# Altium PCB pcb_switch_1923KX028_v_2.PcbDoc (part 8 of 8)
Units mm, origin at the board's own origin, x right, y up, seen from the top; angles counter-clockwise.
Board outline 297.2 x 112.05 mm, 6 copper layers (Component Side, GND Layer 1, Inner Layer 1, Inner Layer 2, GND Layer 2, Solder Side), stack 1.578 mm thick; 545 components, 377 nets, 3174 pads, 1537 vias.
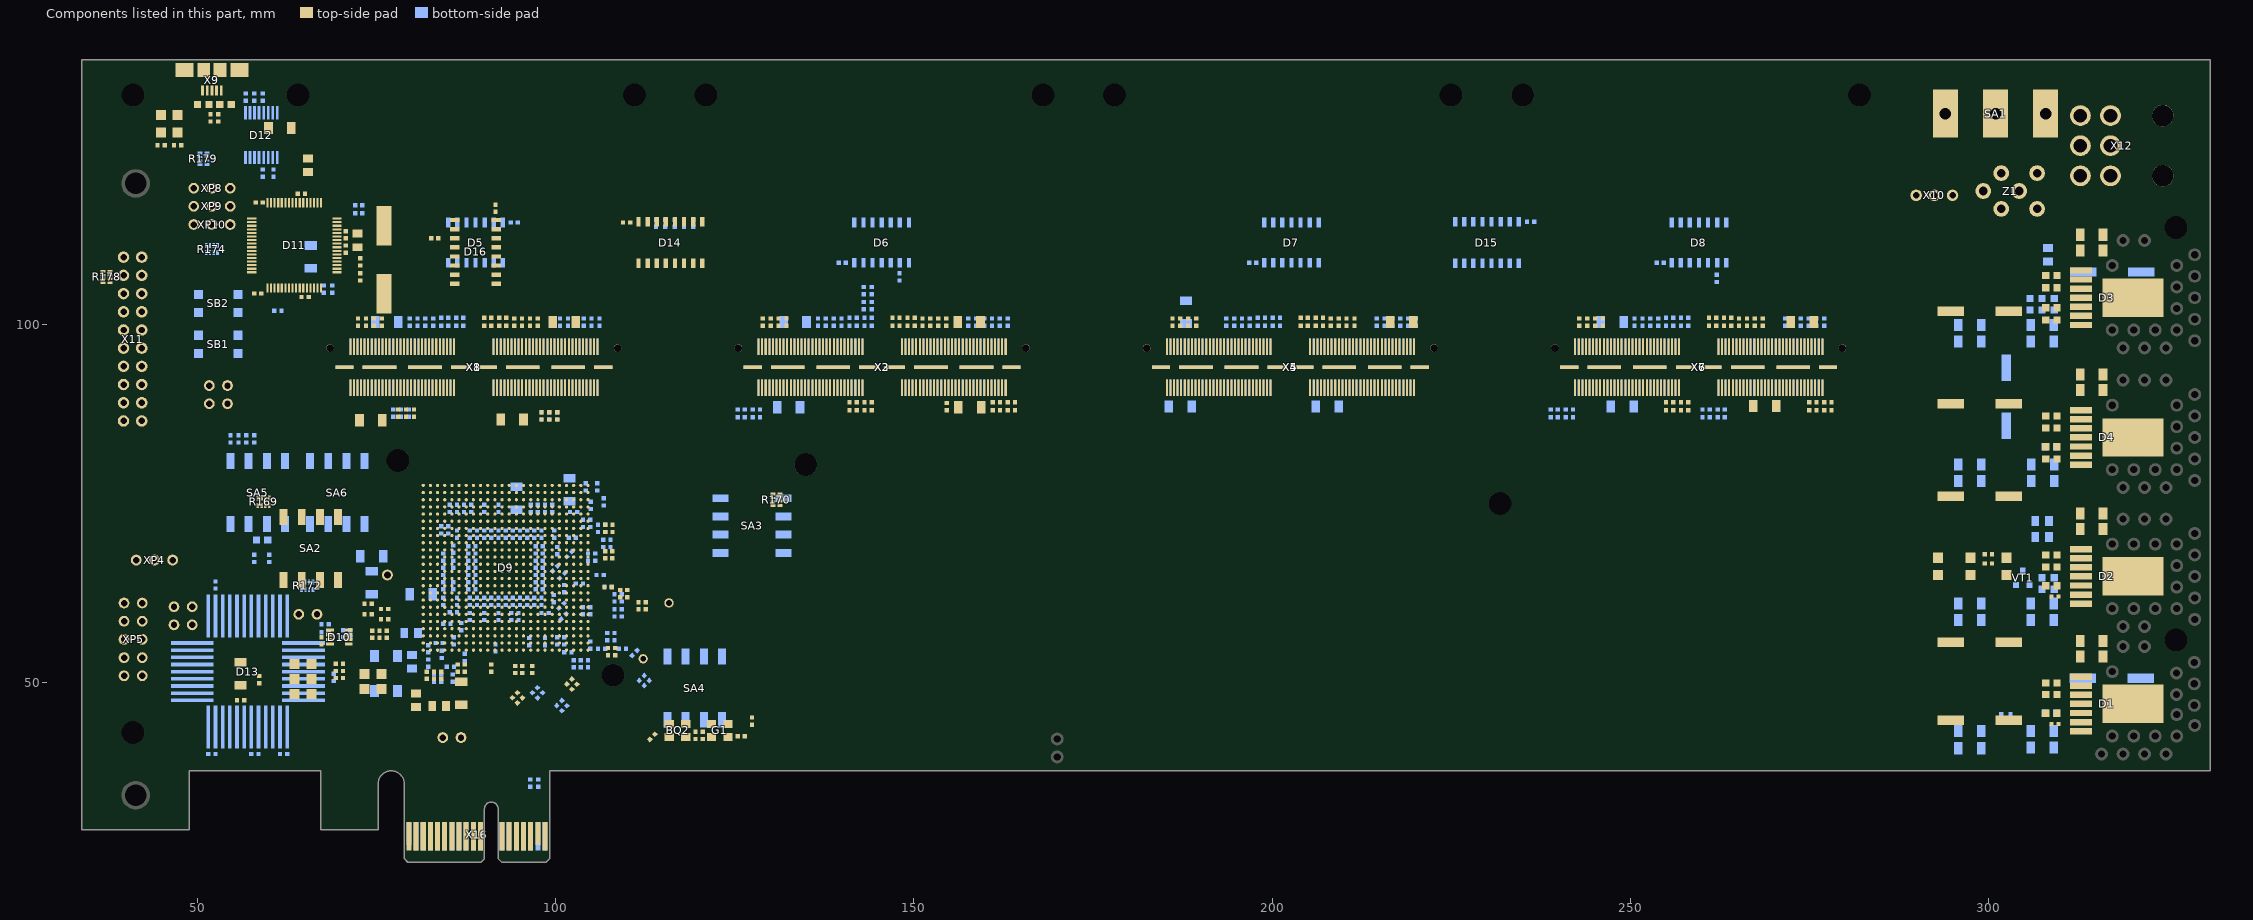
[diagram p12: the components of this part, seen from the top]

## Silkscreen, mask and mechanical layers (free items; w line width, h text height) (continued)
Mechanical 1:
  circle w0.18: c326.2,55.9 r1.6
  circle w0.18: c326.2,113.5 r1.6
  circle w0.18: c231.8,75 r1.6
  circle w0.18: c108,51 r1.6
  circle w0.18: c41.4,34.3 r1.6
  circle w0.18: c41,43 r1.6
  circle w0.18: c78,81 r1.6
  circle w0.18: c41.4,119.7 r1.6
  circle w0.18: c41,132 r1.6
  lines w0.15: 34.4,30.2 43.7,30.2 ccw(c43.7,31.2) 44.7,31.2 44.7,37.3 ccw(c43.7,37.3) 43.7,38.3 34.4,38.3 ; 34.4,115.6 43.7,115.6 ccw(c43.7,116.6) 44.7,116.6 44.7,122.7 ccw(c43.7,122.7) 43.7,123.7 34.4,123.7
  lines w0.2: 79.25,26.6 79.25,30.4 79.75,30.4 79.75,26.6 79.25,26.6 ; 80.25,26.6 80.75,26.6 80.75,30.4 80.25,30.4 80.25,26.6 ; 81.25,26.6 81.75,26.6 81.75,30.4 81.25,30.4 81.25,26.6 ; 82.25,26.6 82.75,26.6 82.75,30.4 82.25,30.4 82.25,26.6 ; 83.25,26.6 83.75,26.6 83.75,30.4 83.25,30.4 83.25,26.6 ; 84.25,26.6 84.75,26.6 84.75,30.4 84.25,30.4 84.25,26.6 ; 85.25,26.6 85.75,26.6 85.75,30.4 85.25,30.4 85.25,26.6 ; 86.25,26.6 86.75,26.6 86.75,30.4 86.25,30.4 86.25,26.6 ; 87.25,26.6 87.75,26.6 87.75,30.4 87.25,30.4 87.25,26.6 ; 88.25,26.6 88.75,26.6 88.75,30.4 88.25,30.4 88.25,26.6 ; 89.25,26.6 89.75,26.6 89.75,30.4 89.25,30.4 89.25,26.6 ; 92.25,26.6 92.75,26.6 92.75,30.4 92.25,30.4 92.25,26.6 ; 93.25,26.6 93.75,26.6 93.75,30.4 93.25,30.4 93.25,26.6 ; 94.25,26.6 94.75,26.6 94.75,30.4 94.25,30.4 94.25,26.6 ; 95.25,26.6 95.75,26.6 95.75,30.4 95.25,30.4 95.25,26.6 ; 96.25,26.6 96.75,26.6 96.75,30.4 96.25,30.4 96.25,26.6 ; 97.25,27.4 97.75,27.4 97.75,30.4 97.25,30.4 97.25,27.4 ; 98.25,26.6 98.75,26.6 98.75,30.4 98.25,30.4 98.25,26.6
  lines w0.254: 318.15,118.025 318.15,119.625 ; 318.15,121.875 318.15,123.75 ; 318.15,126 318.15,127.875 ; 318.15,130.25 318.15,131.825
Mechanical 2:
  circle w0.18: c134.9,80.4 r1.562
  circle w0.18: c64,132 r1.562
  circle w0.18: c121,132 r1.562
  circle w0.18: c111,132 r1.562
  circle w0.18: c168,132 r1.562
  circle w0.18: c178,132 r1.562
  circle w0.18: c225,132 r1.562
  circle w0.18: c235,132 r1.562
  circle w0.18: c282,132 r1.562
  circle w0.18: c326.2,113.5 r1.562
  circle w0.18: c326.2,55.9 r1.562
  circle w0.18: c231.8,75 r1.562
  circle w0.18: c78,81 r1.562
  circle w0.18: c108,51 r1.562
  circle w0.18: c41,43 r1.562
  circle w0.18: c41.4,34.3 r1.562
  circle w0.18: c41.4,119.7 r1.562
  circle w0.18: c41,132 r1.562
  circle w0.18: c269,113.5 r1.562
  lines w0.15: 78.85,26.3 90.05,26.3 ; 91.95,26.3 99.15,26.3
  lines w0.2: 79.25,27.4 79.75,27.4 79.75,30.4 79.25,30.4 79.25,27.4 ; 80.25,26.6 80.75,26.6 80.75,30.4 80.25,30.4 80.25,26.6 ; 81.25,26.6 81.75,26.6 81.75,30.4 81.25,30.4 81.25,26.6 ; 82.25,26.6 82.75,26.6 82.75,30.4 82.25,30.4 82.25,26.6 ; 83.25,26.6 83.75,26.6 83.75,30.4 83.25,30.4 83.25,26.6 ; 84.25,26.6 84.75,26.6 84.75,30.4 84.25,30.4 84.25,26.6 ; 85.25,26.6 85.75,26.6 85.75,30.4 85.25,30.4 85.25,26.6 ; 86.25,26.6 86.75,26.6 86.75,30.4 86.25,30.4 86.25,26.6 ; 87.25,26.6 87.75,26.6 87.75,30.4 87.25,30.4 87.25,26.6 ; 88.25,26.6 88.75,26.6 88.75,30.4 88.25,30.4 88.25,26.6 ; 89.25,26.6 89.75,26.6 89.75,30.4 89.25,30.4 89.25,26.6 ; 92.25,26.6 92.75,26.6 92.75,30.4 92.25,30.4 92.25,26.6 ; 93.25,26.6 93.75,26.6 93.75,30.4 93.25,30.4 93.25,26.6 ; 94.25,26.6 94.75,26.6 94.75,30.4 94.25,30.4 94.25,26.6 ; 95.25,26.6 95.75,26.6 95.75,30.4 95.25,30.4 95.25,26.6 ; 96.25,26.6 96.75,26.6 96.75,30.4 96.25,30.4 96.25,26.6 ; 97.25,26.6 97.75,26.6 97.75,30.4 97.25,30.4 97.25,26.6 ; 98.25,26.6 98.25,30.4 98.75,30.4 98.75,26.6 98.25,26.6
Mechanical 3:
  the board outline again, w0.2
Mechanical 4:
  lines w0.15: 103,56 103.5,56.5 111.5,56.5 113.9,54.1 113.9,53.6 114.5,53 119.5,53 ; 103,57 103.6,57.6 112.1,57.6 116.2,53.5 117,53.5 ; 104,56 111.3,56 113.5,53.8 113.5,53.4 114,52.9 114,52.6 114.2,52.4 117,52.4 125.1,44.3 ; 104,57 111.8,57 114.5,54.3 114.5,53.9
  text "Стек печатной платы: /   материал: «Kingboard»KB-6167F (Tg170) /   ядро: FR-4, 0.51 ± 0.05 mm,  Dk: 4.7 /   препрег: prepreg 1080, 0.069 ± 0.008 mm, Dk: 4.2 ± 0.25 /    /  6-ти слойная печатная плата: /     Top layer: 0.018 mm  /         2 x prepreg 1080 (0.15 mm) /     GND 1  layer: 0.018 mm /         Core: 0.51 mm /     Inner 1 Layer: 0.018 mm /         2 x prepreg 1080 (0.15 mm) /     Inner 2 Layer: 0.018 mm /         Core: 0.51 mm /     GND 2  Layer: 0.018 mm  /         2 x prepreg 1080 (0.015 mm) /     Bottom Layer 0.018 mm /      / Дифф. пара: /     ширина трассы (W): 0.15 мм /     расстояние между трассами (S): 0.16 мм /     расстояние до полигона \"GND\" (D1): 0.20 мм /     толщина медной фольги (Т1): 0.018 мм (0.045 мм после металлизации) /  / Дополнительные механические слои: / Mechanical 21 (top), 27 (bottom) - желтый цвет, 100 нФ, 10В, 0402 / Mechanical 22 (top), 28 (bottom) - красный цвет, 1 мкФ, 10В, 0402 / Mechanical 23 (top), 29 (bottom) - зеленый цвет, 10 нФ, 25В, 0402 / Mechanical 24 (top), 30 (bottom) - синий цвет, 1 нФ, 50В, 0402 / Mechanical 25 (top), 31 (bottom) - малиновый цвет, 11 кОм, 1%, 0402 / Mechanical 26 (top), 32 (bottom) - голубой цвет, 2.49 кОм, 1%, 0402" at 339.4,24.3 h5
Mechanical 21:
  rectangle: 308.4,43.8 310.2,44.6
  rectangle: 308.4,61.6 310.2,62.4
  rectangle: 109,113.8 110.8,114.6
  region: 91.2,117.1 91.2,115.3 92,115.3 92,117.1
  region: 93.9,52.7 93.9,50.9 94.7,50.9 94.7,52.7
  region: 94.9,52.7 94.9,50.9 95.7,50.9 95.7,52.7
  rectangle: 111.2,59.8 113,60.6
  rectangle: 111.2,60.8 113,61.6
  region: 101.7,50.4 102.973,49.127 103.538,49.693 102.266,50.966
  region: 101,49.7 102.273,48.427 102.838,48.993 101.566,50.266
  rectangle: 106.9,53.4 108.7,54.2
  rectangle: 106.9,54.4 108.7,55.2
  region: 106.5,72.4 106.5,70.6 107.3,70.6 107.3,72.4
  region: 107.5,72.4 107.5,70.6 108.3,70.6 108.3,72.4
  region: 93.4,47.8 94.673,46.527 95.238,47.093 93.966,48.366
  rectangle: 108.6,61.5 110.4,62.3
  region: 94.1,48.5 95.373,47.227 95.938,47.793 94.666,49.066
  rectangle: 108.6,62.5 110.4,63.3
  region: 66.9,56.7 66.9,54.9 67.7,54.9 67.7,56.7
  region: 70.3,111.4 70.3,109.6 71.1,109.6 71.1,111.4
  region: 70.3,113.4 70.3,111.6 71.1,111.6 71.1,113.4
  rectangle: 57.5,103.9 59.3,104.7
  rectangle: 64.1,103.4 65.9,104.2
  rectangle: 57.7,116.6 59.5,117.4
  rectangle: 63.6,117.8 65.4,118.6
  rectangle: 106.5,67.9 108.3,68.7
  rectangle: 106.5,66.9 108.3,67.7
  region: 86.9,52.9 86.9,51.1 87.7,51.1 87.7,52.9
  rectangle: 106.4,62.9 108.2,63.7
  region: 90.6,52.9 90.6,51.1 91.4,51.1 91.4,52.9
  rectangle: 125,42.1 126.8,42.9
Mechanical 22:
  rectangle: 96.3,50.9 97.1,52.7
  rectangle: 85.9,51.1 86.7,52.9
  region: 56.9,47.1 56.9,47.9 55.1,47.9 55.1,47.1
Mechanical 25:
  rectangle: 79.8,86.7 80.6,88.5
  rectangle: 77.6,86.7 78.4,88.5
  region: 142.4,87.6 142.4,88.4 140.6,88.4 140.6,87.6
  region: 144.5,87.6 144.5,88.4 142.7,88.4 142.7,87.6
  region: 162.4,88.7 162.4,89.5 160.6,89.5 160.6,88.7
  region: 164.5,88.7 164.5,89.5 162.7,89.5 162.7,88.7
  region: 256.4,88.7 256.4,89.5 254.6,89.5 254.6,88.7
  region: 258.5,88.7 258.5,89.5 256.7,89.5 256.7,88.7
  region: 276.4,88.7 276.4,89.5 274.6,89.5 274.6,88.7
  region: 278.5,88.7 278.5,89.5 276.7,89.5 276.7,88.7
  region: 59,51.3 58.2,51.3 58.2,49.5 59,49.5
  region: 84.4,51.9 83.6,51.9 83.6,50.1 84.4,50.1
  region: 127.8,45.5 127,45.5 127,43.7 127.8,43.7
  region: 79.5,88.5 78.7,88.5 78.7,86.7 79.5,86.7
  region: 98.4,88.1 97.6,88.1 97.6,86.3 98.4,86.3
  region: 99.5,88.1 98.7,88.1 98.7,86.3 99.5,86.3
  region: 100.6,88.1 99.8,88.1 99.8,86.3 100.6,86.3
  region: 82.2,112.4 82.2,111.6 84,111.6 84,112.4
Mechanical 26:
  rectangle: 140.6,88.7 142.4,89.5
  rectangle: 142.7,88.7 144.5,89.5
  rectangle: 89.6,99.4 91.4,100.2
  rectangle: 91.7,99.4 93.5,100.2
  rectangle: 146.6,99.4 148.4,100.2
  rectangle: 148.7,99.4 150.5,100.2
  rectangle: 160.6,87.6 162.4,88.4
  rectangle: 162.7,87.6 164.5,88.4
  rectangle: 254.6,87.6 256.4,88.4
  rectangle: 256.7,87.6 258.5,88.4
  rectangle: 203.6,99.4 205.4,100.2
  rectangle: 205.7,99.4 207.5,100.2
  rectangle: 260.6,99.4 262.4,100.2
  rectangle: 262.7,99.4 264.5,100.2
  rectangle: 274.6,87.6 276.4,88.4
  rectangle: 276.7,87.6 278.5,88.4
  region: 72.8,99.4 72.8,101.2 72,101.2 72,99.4
  region: 73.9,99.4 73.9,101.2 73.1,101.2 73.1,99.4
  region: 75,99.4 75,101.2 74.2,101.2 74.2,99.4
  region: 76.1,99.4 76.1,101.2 75.3,101.2 75.3,99.4
  region: 94.6,99.4 94.6,101.2 93.8,101.2 93.8,99.4
  region: 129.3,99.4 129.3,101.2 128.5,101.2 128.5,99.4
  region: 130.4,99.4 130.4,101.2 129.6,101.2 129.6,99.4
  region: 131.5,99.4 131.5,101.2 130.7,101.2 130.7,99.4
  region: 132.6,99.4 132.6,101.2 131.8,101.2 131.8,99.4
  region: 95.7,99.4 95.7,101.2 94.9,101.2 94.9,99.4
  region: 96.8,99.4 96.8,101.2 96,101.2 96,99.4
  region: 97.9,99.4 97.9,101.2 97.1,101.2 97.1,99.4
  region: 151.6,99.4 151.6,101.2 150.8,101.2 150.8,99.4
  region: 154.9,99.4 154.9,101.2 154.1,101.2 154.1,99.4
  region: 152.7,99.4 152.7,101.2 151.9,101.2 151.9,99.4
  region: 153.8,99.4 153.8,101.2 153,101.2 153,99.4
  region: 186.5,99.4 186.5,101.2 185.7,101.2 185.7,99.4
  region: 187.6,99.4 187.6,101.2 186.8,101.2 186.8,99.4
  region: 188.7,99.4 188.7,101.2 187.9,101.2 187.9,99.4
  region: 189.8,99.4 189.8,101.2 189,101.2 189,99.4
  region: 208.6,99.4 208.6,101.2 207.8,101.2 207.8,99.4
  region: 209.7,99.4 209.7,101.2 208.9,101.2 208.9,99.4
  region: 210.8,99.4 210.8,101.2 210,101.2 210,99.4
  region: 211.9,99.4 211.9,101.2 211.1,101.2 211.1,99.4
  region: 243.3,99.4 243.3,101.2 242.5,101.2 242.5,99.4
  region: 244.4,99.4 244.4,101.2 243.6,101.2 243.6,99.4
  region: 245.5,99.4 245.5,101.2 244.7,101.2 244.7,99.4
  region: 246.6,99.4 246.6,101.2 245.8,101.2 245.8,99.4
  region: 265.6,99.4 265.6,101.2 264.8,101.2 264.8,99.4
  region: 266.7,99.4 266.7,101.2 265.9,101.2 265.9,99.4
  region: 267.8,99.4 267.8,101.2 267,101.2 267,99.4
  region: 268.9,99.4 268.9,101.2 268.1,101.2 268.1,99.4
Mechanical 27:
  rectangle: 235.2,113.9 237,114.7
  rectangle: 93.3,113.8 95.1,114.6
  rectangle: 139.1,108.2 140.9,109
  rectangle: 196.4,108.2 198.2,109
  rectangle: 253.3,108.2 255.1,109
  region: 99.6,46.7 100.873,45.427 101.438,45.993 100.166,47.266
  region: 100.3,47.4 101.573,46.127 102.138,46.693 100.866,47.966
  region: 56.3,132.6 56.3,130.8 57.1,130.8 57.1,132.6
  region: 58.7,132.6 58.7,130.8 59.5,130.8 59.5,132.6
  region: 57.5,132.6 57.5,130.8 58.3,130.8 58.3,132.6
  rectangle: 107.8,58.8 109.6,59.6
  rectangle: 107.8,59.8 109.6,60.6
  rectangle: 106.8,55.5 108.6,56.3
  rectangle: 106.8,56.5 108.6,57.3
  rectangle: 106.2,68.5 108,69.3
  rectangle: 106.2,69.5 108,70.3
  region: 96.2,48.5 97.473,47.227 98.038,47.793 96.766,49.066
  rectangle: 107.8,60.9 109.6,61.7
  region: 96.9,49.2 98.173,47.927 98.738,48.493 97.466,49.766
  rectangle: 107.8,61.9 109.6,62.7
  region: 111.7,49.7 112.973,50.973 112.407,51.538 111.134,50.266
  region: 112.4,49 113.673,50.273 113.107,50.838 111.834,49.566
  region: 96.8,35.1 96.8,36.9 96,36.9 96,35.1
  region: 98,35.1 98,36.9 97.2,36.9 97.2,35.1
  region: 90.4,60.4 90.4,62.2 89.6,62.2 89.6,60.4
  region: 96.4,60.4 96.4,62.2 95.6,62.2 95.6,60.4
  region: 93.4,60.4 93.4,62.2 92.6,62.2 92.6,60.4
  region: 89.2,63.4 87.4,63.4 87.4,62.6 89.2,62.6
  region: 98.6,63.4 96.8,63.4 96.8,62.6 98.6,62.6
  region: 89.2,67.4 87.4,67.4 87.4,66.6 89.2,66.6
  region: 98.6,67.4 96.8,67.4 96.8,66.6 98.6,66.6
  region: 95.6,71.6 95.6,69.8 96.4,69.8 96.4,71.6
  region: 92.6,71.6 92.6,69.8 93.4,69.8 93.4,71.6
  region: 89.6,71.6 89.6,69.8 90.4,69.8 90.4,71.6
  rectangle: 108.4,54.3 110.2,55.1
  rectangle: 97.6,59.3 99.4,60.1
  region: 100.5,64 101.773,65.273 101.207,65.838 99.934,64.566
  region: 104.6,76.4 104.6,78.2 103.8,78.2 103.8,76.4
  region: 86.1,65.6 86.1,67.4 85.3,67.4 85.3,65.6
  region: 92.4,73.4 92.4,75.2 91.6,75.2 91.6,73.4
  region: 87.6,73.4 87.6,75.2 86.8,75.2 86.8,73.4
  region: 86,49.7 86,51.5 85.2,51.5 85.2,49.7
  region: 86.6,73.4 86.6,75.2 85.8,75.2 85.8,73.4
  region: 86.1,67.7 86.1,69.5 85.3,69.5 85.3,67.7
  region: 84.7,60.4 84.7,62.2 83.9,62.2 83.9,60.4
  region: 88.4,58.3 88.4,60.1 87.6,60.1 87.6,58.3
  region: 94.2,58.3 94.2,60.1 93.4,60.1 93.4,58.3
  region: 98.9,73.4 98.9,75.2 98.1,75.2 98.1,73.4
  region: 105.9,68.4 104.1,68.4 104.1,67.6 105.9,67.6
  region: 105.9,67.4 104.1,67.4 104.1,66.6 105.9,66.6
  region: 86.2,52.6 84.4,52.6 84.4,51.8 86.2,51.8
  region: 83.7,54.8 83.7,53 84.5,53 84.5,54.8
  rectangle: 103.4,71.3 105.2,72.1
  rectangle: 102.4,63.4 104.2,64.2
  rectangle: 103.4,60.1 105.2,60.9
  region: 83.4,49.7 83.4,51.5 82.6,51.5 82.6,49.7
  region: 98.9,54.8 98.9,56.6 98.1,56.6 98.1,54.8
  region: 101.6,55.7 99.8,55.7 99.8,54.9 101.6,54.9
  region: 102.1,53.5 102.1,51.7 102.9,51.7 102.9,53.5
  region: 105.5,72.4 105.5,70.6 106.3,70.6 106.3,72.4
  region: 95.9,56.6 95.9,54.8 96.7,54.8 96.7,56.6
  region: 103.1,53.5 103.1,51.7 103.9,51.7 103.9,53.5
  rectangle: 57.1,39.6 58.9,40.4
  region: 82.6,51.8 82.6,53.6 81.8,53.6 81.8,51.8
Mechanical 28:
  rectangle: 85.8,60.4 86.6,62.2
  rectangle: 99.3,60.8 100.1,62.6
  rectangle: 99.4,69.8 100.2,71.6
  rectangle: 85.8,69.8 86.6,71.6
  rectangle: 83.6,49.7 84.4,51.5
  region: 86.6,59.4 86.6,60.2 84.8,60.2 84.8,59.4
  region: 103.4,73.4 103.4,74.2 101.6,74.2 101.6,73.4
  region: 95.2,60.1 94.4,60.1 94.4,58.3 95.2,58.3
  region: 84.4,72.2 83.6,72.2 83.6,70.4 84.4,70.4
  region: 100.934,67.566 101.5,67 102.773,68.273 102.207,68.838
  rectangle: 89.6,73.4 90.4,75.2
  rectangle: 83.9,66.6 84.7,68.4
  rectangle: 85.4,54.9 86.2,56.7
  region: 105.2,72.3 105.2,73.1 103.4,73.1 103.4,72.3
  region: 107.1,64.6 107.1,65.4 105.3,65.4 105.3,64.6
  region: 101.6,55.9 101.6,56.7 99.8,56.7 99.8,55.9
Mechanical 29:
  rectangle: 104.4,54.3 105.2,56.1
  rectangle: 87.6,60.4 88.4,62.2
  rectangle: 90.6,60.4 91.4,62.2
  rectangle: 93.6,60.4 94.4,62.2
  rectangle: 96.6,60.4 97.4,62.2
  region: 89.2,64.6 89.2,65.4 87.4,65.4 87.4,64.6
  region: 98.6,64.6 98.6,65.4 96.8,65.4 96.8,64.6
  region: 89.2,68.6 89.2,69.4 87.4,69.4 87.4,68.6
  region: 98.6,68.6 98.6,69.4 96.8,69.4 96.8,68.6
  region: 97.4,71.6 96.6,71.6 96.6,69.8 97.4,69.8
  region: 91.4,71.6 90.6,71.6 90.6,69.8 91.4,69.8
  region: 88.4,71.6 87.6,71.6 87.6,69.8 88.4,69.8
  region: 94.4,71.6 93.6,71.6 93.6,69.8 94.4,69.8
  region: 105.3,75.6 104.5,75.6 104.5,73.8 105.3,73.8
  region: 90.4,60.1 89.6,60.1 89.6,58.3 90.4,58.3
  region: 99.9,75.2 99.1,75.2 99.1,73.4 99.9,73.4
  region: 88.6,75.2 87.8,75.2 87.8,73.4 88.6,73.4
  region: 100.6,69.3 99.8,69.3 99.8,67.5 100.6,67.5
  region: 86.1,64.4 85.3,64.4 85.3,62.6 86.1,62.6
Mechanical 30:
  rectangle: 96.1,73.4 96.9,75.2
  region: 89.2,67.6 89.2,68.4 87.4,68.4 87.4,67.6
  region: 89.2,65.6 89.2,66.4 87.4,66.4 87.4,65.6
  region: 89.4,62.2 88.6,62.2 88.6,60.4 89.4,60.4
  region: 98.4,62.2 97.6,62.2 97.6,60.4 98.4,60.4
  region: 92.4,62.2 91.6,62.2 91.6,60.4 92.4,60.4
  region: 87.4,64.4 87.4,63.6 89.2,63.6 89.2,64.4
  region: 96.8,64.4 96.8,63.6 98.6,63.6 98.6,64.4
  region: 96.8,66.4 96.8,65.6 98.6,65.6 98.6,66.4
  region: 96.8,68.4 96.8,67.6 98.6,67.6 98.6,68.4
  rectangle: 97.6,69.8 98.4,71.6
  rectangle: 94.6,69.8 95.4,71.6
  rectangle: 94.6,60.4 95.4,62.2
  rectangle: 91.6,69.8 92.4,71.6
  rectangle: 88.6,69.8 89.4,71.6
  region: 107.3,54.3 107.3,55.1 105.5,55.1 105.5,54.3
  region: 87.2,58.7 86.4,58.7 86.4,56.9 87.2,56.9
  region: 103.4,59.9 103.4,59.1 105.2,59.1 105.2,59.9
  rectangle: 100.8,62.2 101.6,64
  rectangle: 86.9,52.6 87.7,54.4
  region: 101.966,59.534 101.4,60.1 100.127,58.827 100.693,58.262
  region: 101.4,70.6 101.4,69.8 103.2,69.8 103.2,70.6
  rectangle: 104.1,51.7 104.9,53.5
  region: 84.6,55.1 84.6,55.9 82.8,55.9 82.8,55.1
  region: 102.6,53.8 102.6,54.6 100.8,54.6 100.8,53.8
  region: 92,55.7 91.2,55.7 91.2,53.9 92,53.9
  region: 107.3,72.4 106.5,72.4 106.5,70.6 107.3,70.6
  region: 106.4,63.8 106.4,63 108.2,63 108.2,63.8
  rectangle: 84.8,73.4 85.6,75.2
  rectangle: 83.9,62.6 84.7,64.4
  rectangle: 105.4,76.4 106.2,78.2
  rectangle: 97.1,73.4 97.9,75.2
  rectangle: 84.6,70.4 85.4,72.2
  rectangle: 83.9,64.6 84.7,66.4
  region: 100.866,66.234 100.3,66.8 99.027,65.527 99.593,64.962
  region: 101.766,61.034 101.2,61.6 99.927,60.327 100.493,59.762
  region: 92.4,60.1 91.6,60.1 91.6,58.3 92.4,58.3
  region: 82.6,55.6 81.8,55.6 81.8,53.8 82.6,53.8
Mechanical 31:
  rectangle: 71.6,115.1 73.4,115.9
  region: 61,120.2 61,122 60.2,122 60.2,120.2
  region: 59.5,120.2 59.5,122 58.7,122 58.7,120.2
  region: 143.4,103.8 143.4,105.6 142.6,105.6 142.6,103.8
  region: 143.4,101.7 143.4,103.5 142.6,103.5 142.6,101.7
  region: 142.4,101.3 140.6,101.3 140.6,100.5 142.4,100.5
  region: 144.5,101.3 142.7,101.3 142.7,100.5 144.5,100.5
  region: 126.8,88.5 125,88.5 125,87.7 126.8,87.7
  region: 128.9,88.5 127.1,88.5 127.1,87.7 128.9,87.7
  region: 199.4,101.3 197.6,101.3 197.6,100.5 199.4,100.5
  region: 201.5,101.3 199.7,101.3 199.7,100.5 201.5,100.5
  region: 261.5,88.5 259.7,88.5 259.7,87.7 261.5,87.7
  region: 263.6,88.5 261.8,88.5 261.8,87.7 263.6,87.7
  region: 256.4,101.3 254.6,101.3 254.6,100.5 256.4,100.5
  region: 258.5,101.3 256.7,101.3 256.7,100.5 258.5,100.5
  region: 87.5,101.3 85.7,101.3 85.7,100.5 87.5,100.5
  region: 85.4,101.3 83.6,101.3 83.6,100.5 85.4,100.5
  region: 71.7,56.7 69.9,56.7 69.9,55.9 71.7,55.9
  region: 71.7,57.7 69.9,57.7 69.9,56.9 71.7,56.9
  region: 240.3,87.4 238.5,87.4 238.5,86.6 240.3,86.6
  region: 242.4,87.4 240.6,87.4 240.6,86.6 242.4,86.6
  region: 113.6,115 113.6,113.2 114.4,113.2 114.4,115
  region: 114.9,115 114.9,113.2 115.7,113.2 115.7,115
  region: 116.2,115 116.2,113.2 117,113.2 117,115
  region: 117.5,115 117.5,113.2 118.3,113.2 118.3,115
  region: 118.8,115 118.8,113.2 119.6,113.2 119.6,115
  region: 52.1,64.5 52.1,62.7 52.9,62.7 52.9,64.5
  region: 68.6,51.6 68.6,49.8 69.4,49.8 69.4,51.6
  rectangle: 61.1,39.6 62.9,40.4
  rectangle: 51.1,39.6 52.9,40.4
  region: 58.3,66.4 58.3,68.2 57.5,68.2 57.5,66.4
  region: 60.4,66.4 60.4,68.2 59.6,68.2 59.6,66.4
  region: 73.4,117 71.6,117 71.6,116.2 73.4,116.2
  region: 54.2,84.9 54.2,83.1 55,83.1 55,84.9
  region: 55.3,84.9 55.3,83.1 56.1,83.1 56.1,84.9
  region: 56.4,84.9 56.4,83.1 57.2,83.1 57.2,84.9
  region: 57.5,84.9 57.5,83.1 58.3,83.1 58.3,84.9
  region: 67.2,105.8 67.2,104 68,104 68,105.8
  region: 68.4,105.8 68.4,104 69.2,104 69.2,105.8
  rectangle: 60.3,101.5 62.1,102.3
  rectangle: 66.9,57.7 68.7,58.5
  rectangle: 66.9,56.6 68.7,57.4
  region: 107.1,74.3 107.1,76.1 106.3,76.1 106.3,74.3
  region: 77.7,86.7 77.7,88.5 76.9,88.5 76.9,86.7
  region: 78.8,86.7 78.8,88.5 78,88.5 78,86.7
  region: 79.9,86.7 79.9,88.5 79.1,88.5 79.1,86.7
  region: 98.4,86.3 98.4,88.1 97.6,88.1 97.6,86.3
  region: 99.5,86.3 99.5,88.1 98.7,88.1 98.7,86.3
  region: 100.6,86.3 100.6,88.1 99.8,88.1 99.8,86.3
Mechanical 32:
  rectangle: 143.7,103.8 144.5,105.6
  rectangle: 143.7,101.7 144.5,103.5
  rectangle: 161.6,99.4 162.4,101.2
  rectangle: 162.7,99.4 163.5,101.2
  region: 142.4,99.4 142.4,100.2 140.6,100.2 140.6,99.4
  region: 144.5,99.4 144.5,100.2 142.7,100.2 142.7,99.4
  region: 126.8,86.6 126.8,87.4 125,87.4 125,86.6
  region: 128.9,86.6 128.9,87.4 127.1,87.4 127.1,86.6
  region: 219.4,101.2 218.6,101.2 218.6,99.4 219.4,99.4
  region: 220.5,101.2 219.7,101.2 219.7,99.4 220.5,99.4
  region: 197.6,100.2 197.6,99.4 199.4,99.4 199.4,100.2
  region: 199.7,100.2 199.7,99.4 201.5,99.4 201.5,100.2
  rectangle: 275.6,99.4 276.4,101.2
  rectangle: 276.7,99.4 277.5,101.2
  rectangle: 104.6,99.4 105.4,101.2
  rectangle: 105.7,99.4 106.5,101.2
  region: 85.4,99.4 85.4,100.2 83.6,100.2 83.6,99.4
  region: 87.5,99.4 87.5,100.2 85.7,100.2 85.7,99.4
  region: 256.4,99.4 256.4,100.2 254.6,100.2 254.6,99.4
  region: 258.5,99.4 258.5,100.2 256.7,100.2 256.7,99.4
  region: 261.5,86.6 261.5,87.4 259.7,87.4 259.7,86.6
  region: 263.6,86.6 263.6,87.4 261.8,87.4 261.8,86.6
  region: 240.3,87.7 240.3,88.5 238.5,88.5 238.5,87.7
  region: 242.4,87.7 242.4,88.5 240.6,88.5 240.6,87.7
  region: 158,101.2 157.2,101.2 157.2,99.4 158,99.4
  region: 159.1,101.2 158.3,101.2 158.3,99.4 159.1,99.4
  region: 160.2,101.2 159.4,101.2 159.4,99.4 160.2,99.4
  region: 161.3,101.2 160.5,101.2 160.5,99.4 161.3,99.4
  region: 140.3,101.2 139.5,101.2 139.5,99.4 140.3,99.4
  region: 139.2,101.2 138.4,101.2 138.4,99.4 139.2,99.4
  region: 138.1,101.2 137.3,101.2 137.3,99.4 138.1,99.4
  region: 137,101.2 136.2,101.2 136.2,99.4 137,99.4
  region: 80,101.2 79.2,101.2 79.2,99.4 80,99.4
  region: 81.1,101.2 80.3,101.2 80.3,99.4 81.1,99.4
  region: 82.2,101.2 81.4,101.2 81.4,99.4 82.2,99.4
  region: 83.3,101.2 82.5,101.2 82.5,99.4 83.3,99.4
  region: 101,101.2 100.2,101.2 100.2,99.4 101,99.4
  region: 102.1,101.2 101.3,101.2 101.3,99.4 102.1,99.4
  region: 103.2,101.2 102.4,101.2 102.4,99.4 103.2,99.4
  region: 104.3,101.2 103.5,101.2 103.5,99.4 104.3,99.4
  region: 194,101.2 193.2,101.2 193.2,99.4 194,99.4
  region: 195.1,101.2 194.3,101.2 194.3,99.4 195.1,99.4
  region: 196.2,101.2 195.4,101.2 195.4,99.4 196.2,99.4
  region: 197.3,101.2 196.5,101.2 196.5,99.4 197.3,99.4
  region: 215,101.2 214.2,101.2 214.2,99.4 215,99.4
  region: 216.1,101.2 215.3,101.2 215.3,99.4 216.1,99.4
  region: 217.2,101.2 216.4,101.2 216.4,99.4 217.2,99.4
  region: 218.3,101.2 217.5,101.2 217.5,99.4 218.3,99.4
  region: 251,101.2 250.2,101.2 250.2,99.4 251,99.4
  region: 252.1,101.2 251.3,101.2 251.3,99.4 252.1,99.4
  region: 253.2,101.2 252.4,101.2 252.4,99.4 253.2,99.4
  region: 254.3,101.2 253.5,101.2 253.5,99.4 254.3,99.4
  region: 272,101.2 271.2,101.2 271.2,99.4 272,99.4
  region: 273.1,101.2 272.3,101.2 272.3,99.4 273.1,99.4
  region: 274.2,101.2 273.4,101.2 273.4,99.4 274.2,99.4
  region: 275.3,101.2 274.5,101.2 274.5,99.4 275.3,99.4

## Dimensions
33.8,136.95 to 33.8,29.4 on Mechanical 4
33.8,136.95 to 331,136.95 on Mechanical 4
79.35,24.9 to 33.8,136.95 on Mechanical 4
